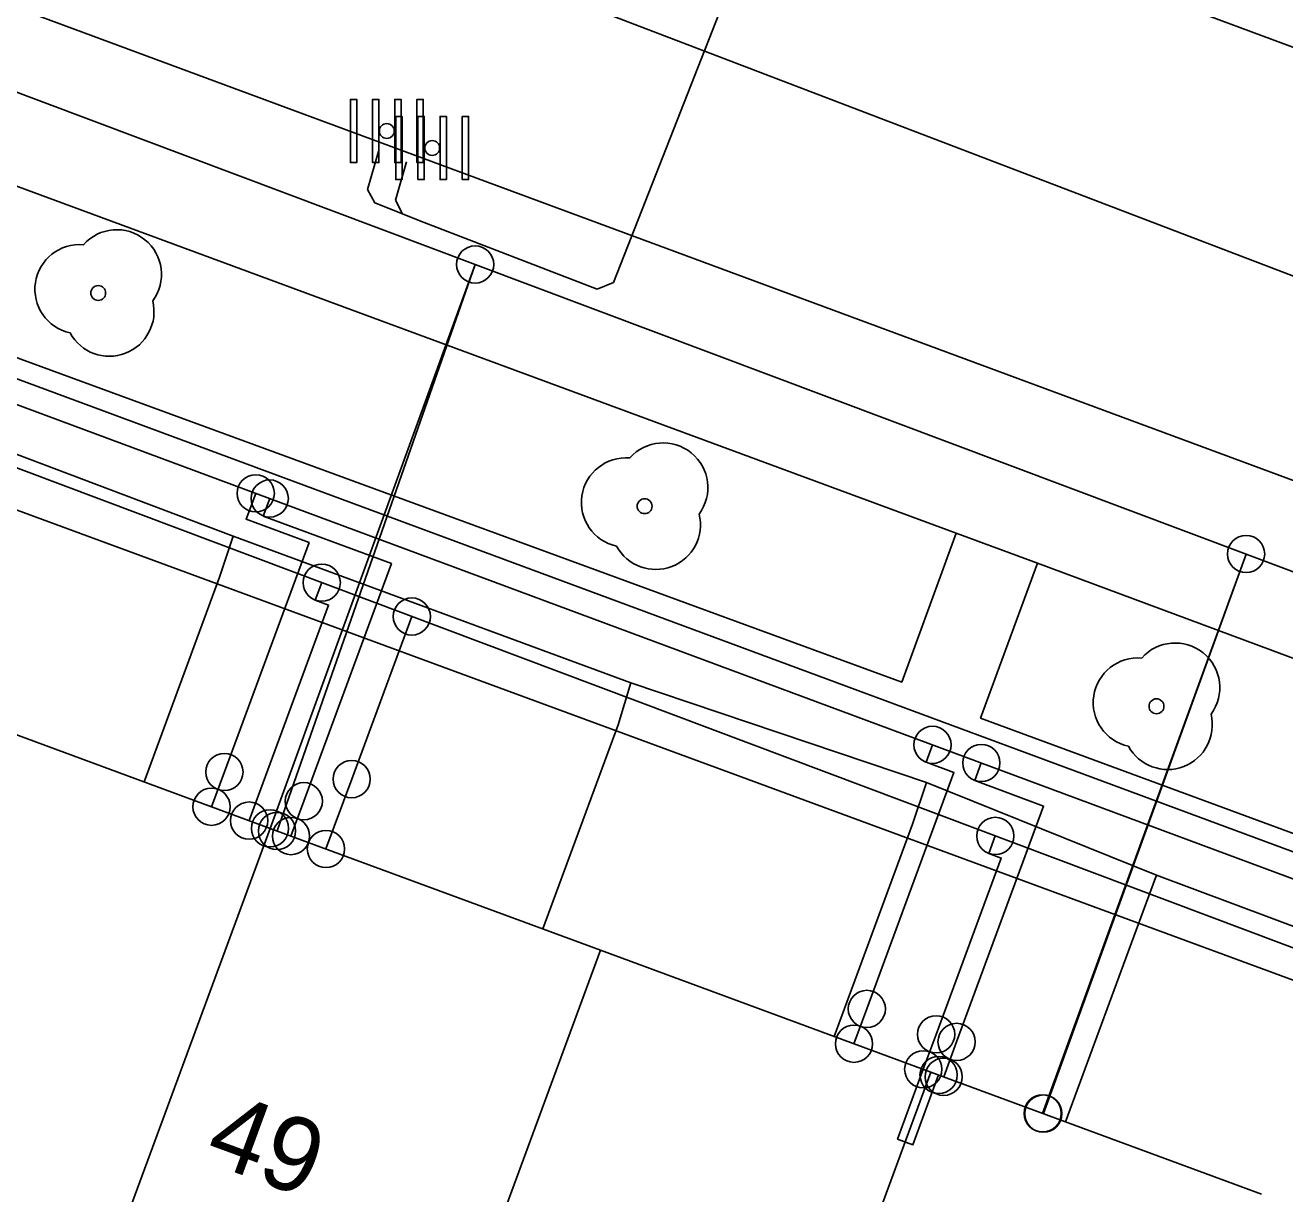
# Model space of a CAD drawing. Extents: x 192672 to 192910, y 446344 to 446512.
# Drawn here: x 192686.52 to 192703.44, y 446398.88 to 446414.58 of the extents above; entities that cross this region are included whole.
import ezdxf

# ---------------------------------------------------------------- set-up
doc = ezdxf.new("R2010")
doc.units = 0
for name, color, linetype in [('B-OI-KL-BUISLEIDING_OLIEGASCHEMICALIEN_GASLAGEDRUK-G', 7, 'Continuous'), ('B-OI-KL-DATA-G', 7, 'Continuous'), ('B-OI-KL-DATA_GTWP-S', 7, 'Continuous'), ('B-OI-KL-DATA_KABELBED-G', 7, 'Continuous'), ('B-OI-KL-DATA_MOF-S', 7, 'Continuous'), ('B-OI-KL-ET_LS-G', 7, 'Continuous'), ('B-OI-KL-ET_LS_DELIVERYPOINT-S', 7, 'Continuous'), ('B-OI-KL-ET_LS_MOF-S', 7, 'Continuous'), ('B-OI-KL-GAS_LD_AFTAKZADEL-S', 7, 'Continuous'), ('B-OI-KL-GAS_LD_DELIVERYPOINT-S', 7, 'Continuous'), ('B-OI-KL-GAS_LD_OVERGANGSSTUK-S', 7, 'Continuous'), ('B-OI-RI-RIOOLVRIJVERVAL-G', 7, 'Continuous'), ('boom', 7, 'Continuous'), ('Default', 7, 'Continuous'), ('huisnummerreeks BGT', 7, 'Continuous'), ('kant open verharding', 7, 'Continuous'), ('kant verharding', 7, 'Continuous'), ('kolk', 7, 'Continuous'), ('pand op maaiveld vlak', 7, 'Continuous'), ('verkeerseiland - berm', 7, 'Continuous')]:
    doc.layers.add(name, color=color, linetype=linetype)

# ---------------------------------------------------------------- blocks, each defined once
blk = doc.blocks.new('B-OI-KL-GAS_LD_AFTAKZADEL-S')
at = {"layer": 'Default'}
blk.add_circle((0, 0), 0.25, dxfattribs=at)
blk = doc.blocks.new('B-OI-KL-GAS_LD_DELIVERYPOINT-S')
at = {"layer": 'Default'}
blk.add_circle((0, 0), 0.25, dxfattribs=at)
blk = doc.blocks.new('B-OI-KL-GAS_LD_OVERGANGSSTUK-S')
at = {"layer": 'Default'}
blk.add_circle((0, 0), 0.25, dxfattribs=at)
blk = doc.blocks.new('B-OI-KL-ET_LS_DELIVERYPOINT-S')
at = {"layer": 'Default'}
blk.add_circle((0, 0), 0.25, dxfattribs=at)
blk = doc.blocks.new('B-OI-KL-ET_LS_MOF-S')
at = {"layer": 'Default'}
blk.add_circle((0, 0), 0.25, dxfattribs=at)
blk = doc.blocks.new('B-OI-KL-DATA_GTWP-S')
at = {"layer": 'Default'}
blk.add_circle((0, 0), 0.25, dxfattribs=at)
blk = doc.blocks.new('B-OI-KL-DATA_MOF-S')
at = {"layer": 'Default'}
blk.add_circle((0, 0), 0.25, dxfattribs=at)

msp = doc.modelspace()

# ---------------------------------------------------------------- linework, layer by layer
at = {"layer": 'B-OI-KL-BUISLEIDING_OLIEGASCHEMICALIEN_GASLAGEDRUK-G'}
msp.add_line((192675.743, 446413.446), (192709.208, 446401.012), dxfattribs=at)
for points in [[(192689.616, 446408.292), (192689.487, 446407.946), (192690.332, 446407.632), (192689.195, 446404.549)], [(192689.804, 446408.223), (192689.716, 446407.988), (192691.439, 446407.349), (192690.262, 446404.157)], [(192698.709, 446404.914), (192698.622, 446404.68), (192698.997, 446404.54), (192697.827, 446401.366)], [(192689.195, 446404.549), (192689.022, 446404.082)], [(192699.365, 446404.67), (192699.278, 446404.436), (192700.202, 446404.092), (192699.033, 446400.923)], [(192690.262, 446404.157), (192690.089, 446403.688)], [(192697.827, 446401.366), (192697.654, 446400.898)], [(192699.033, 446400.923), (192698.86, 446400.454)]]:
    msp.add_lwpolyline(points, dxfattribs=at)
at = {"layer": 'B-OI-KL-DATA-G'}
for points in [[(192685.635, 446409.106), (192689.311, 446407.716)], [(192689.311, 446407.716), (192689.13, 446407.165), (192688.116, 446404.416)], [(192689.311, 446407.716), (192694.658, 446405.746)], [(192694.658, 446405.746), (192694.485, 446405.183), (192693.474, 446402.441)], [(192694.658, 446405.746), (192698.63, 446404.409)], [(192698.63, 446404.409), (192698.441, 446403.846), (192697.389, 446400.996)], [(192698.63, 446404.409), (192701.719, 446403.161)], [(192701.719, 446403.161), (192701.541, 446402.678), (192700.498, 446399.849)], [(192701.719, 446403.161), (192707.348, 446401.058)]]:
    msp.add_lwpolyline(points, dxfattribs=at)
at = {"layer": 'B-OI-KL-DATA_KABELBED-G'}
for points in [[(192733.82, 446395.718), (192726.444, 446398.553), (192717.381, 446402.036), (192715.981, 446402.574), (192711.535, 446404.244), (192702.923, 446407.477), (192692.564, 446411.367), (192684.205, 446414.506), (192682.207, 446415.256), (192682.206, 446415.257), (192675.743, 446417.684)], [(192692.564, 446411.367), (192689.808, 446403.792)], [(192692.564, 446411.367), (192689.902, 446403.757)], [(192702.923, 446407.477), (192700.189, 446399.963)], [(192702.923, 446407.477), (192700.199, 446399.96)]]:
    msp.add_lwpolyline(points, dxfattribs=at)
at = {"layer": 'B-OI-KL-ET_LS-G'}
for points in [[(192705.001, 446404.897), (192704.48, 446404.329), (192704.196, 446403.239), (192682.97, 446411.104), (192687.329, 446422.57), (192687.898, 446423.091)], [(192675.743, 446412.643), (192733.67, 446390.862), (192732.765, 446387.575)], [(192690.503, 446407.093), (192690.415, 446406.859), (192690.595, 446406.791), (192689.527, 446403.896)], [(192691.713, 446406.638), (192690.905, 446404.453)], [(192690.905, 446404.453), (192690.559, 446403.515)], [(192699.553, 446403.69), (192699.465, 446403.456), (192699.632, 446403.393), (192698.758, 446401.024)], [(192698.758, 446401.024), (192698.585, 446400.555)], [(192698.585, 446400.555), (192698.239, 446399.617), (192698.445, 446399.541), (192698.791, 446400.479)]]:
    msp.add_lwpolyline(points, dxfattribs=at)
at = {"layer": 'B-OI-RI-RIOOLVRIJVERVAL-G'}
for points in [[(192696.836, 446417.278), (192694.422, 446411.124)], [(192692.66, 446415.38), (192716.55, 446406.25)], [(192691.878, 446411.931), (192691.218, 446412.194), (192691.119, 446412.374), (192691.266, 446412.887)], [(192691.494, 446412.233), (192691.641, 446412.746)], [(192691.59, 446412.046), (192691.494, 446412.233)], [(192694.202, 446411.036), (192691.878, 446411.931)], [(192694.202, 446411.036), (192694.422, 446411.124)]]:
    msp.add_lwpolyline(points, dxfattribs=at)
at = {"layer": 'boom'}
for centre in [(192687.499, 446410.984), (192694.841, 446408.12), (192701.719, 446405.432)]:
    msp.add_circle(centre, 0.1, dxfattribs=at)
for centre, radius, start, end in [((192687.749, 446411.234), 0.6, 323.5446, 138.4658), ((192687.249, 446411.034), 0.6, 85.137, 257.7544), ((192687.499, 446410.984), 0.1, 0, 180), ((192687.499, 446410.984), 0.1, 180, 0), ((192687.649, 446410.734), 0.6, 208.5058, 13.8356), ((192695.091, 446408.37), 0.6, 323.5446, 138.4658), ((192694.591, 446408.17), 0.6, 85.137, 257.7544), ((192694.841, 446408.12), 0.1, 0, 180), ((192694.841, 446408.12), 0.1, 180, 0), ((192694.991, 446407.87), 0.6, 208.5058, 13.8356), ((192701.969, 446405.682), 0.6, 323.5446, 138.4658), ((192701.469, 446405.482), 0.6, 85.137, 257.7544), ((192701.719, 446405.432), 0.1, 0, 180), ((192701.719, 446405.432), 0.1, 180, 0), ((192701.869, 446405.182), 0.6, 208.5058, 13.8356)]:
    msp.add_arc(centre, radius, start, end, dxfattribs=at)
at = {"layer": 'kant open verharding'}
msp.add_lwpolyline([(192675.743, 446411.995), (192713.029, 446398.263), (192714.204, 446397.83), (192714.097, 446397.514)], dxfattribs=at)
at = {"layer": 'kant verharding'}
for p, q in [((192675.743, 446424.623), (192733.082, 446403.313)), ((192675.743, 446418.762), (192731.114, 446398.266)), ((192700.122, 446407.353), (192699.029, 446407.759))]:
    msp.add_line(p, q, dxfattribs=at)
at = {"layer": 'kolk'}
for points in [[(192690.973, 446413.16), (192690.973, 446413.585), (192690.888, 446413.585), (192690.888, 446413.16), (192690.888, 446412.735), (192690.973, 446412.735)], [(192691.271, 446413.16), (192691.271, 446413.585), (192691.186, 446413.585), (192691.186, 446413.16), (192691.186, 446412.735), (192691.271, 446412.735)], [(192691.568, 446413.16), (192691.568, 446413.585), (192691.483, 446413.585), (192691.483, 446413.16), (192691.483, 446412.735), (192691.568, 446412.735)], [(192691.866, 446413.16), (192691.866, 446413.585), (192691.781, 446413.585), (192691.781, 446413.16), (192691.781, 446412.735), (192691.866, 446412.735)], [(192691.583, 446412.932), (192691.583, 446413.357), (192691.498, 446413.357), (192691.498, 446412.932), (192691.498, 446412.507), (192691.583, 446412.507)], [(192691.881, 446412.932), (192691.881, 446413.357), (192691.796, 446413.357), (192691.796, 446412.932), (192691.796, 446412.507), (192691.881, 446412.507)], [(192692.178, 446412.932), (192692.178, 446413.357), (192692.093, 446413.357), (192692.093, 446412.932), (192692.093, 446412.507), (192692.178, 446412.507)], [(192692.476, 446412.932), (192692.476, 446413.357), (192692.391, 446413.357), (192692.391, 446412.932), (192692.391, 446412.507), (192692.476, 446412.507)]]:
    msp.add_lwpolyline(points, close=True, dxfattribs=at)
for centre, start, end in [((192691.377, 446413.16), 0, 180), ((192691.377, 446413.16), 180, 0), ((192691.987, 446412.932), 0, 180), ((192691.987, 446412.932), 180, 0)]:
    msp.add_arc(centre, 0.1, start, end, dxfattribs=at)
at = {"layer": 'pand op maaiveld vlak'}
for p, q in [((192689.808, 446403.792), (192685.368, 446405.43)), ((192689.808, 446403.792), (192685.669, 446392.571)), ((192689.808, 446403.792), (192694.248, 446402.155)), ((192694.248, 446402.155), (192690.11, 446390.934)), ((192694.248, 446402.155), (192698.688, 446400.517)), ((192694.55, 446389.296), (192698.688, 446400.517)), ((192703.129, 446398.879), (192698.688, 446400.517))]:
    msp.add_line(p, q, dxfattribs=at)
at = {"layer": 'verkeerseiland - berm'}
for p, q in [((192699.029, 446407.759), (192683.929, 446413.333)), ((192714.516, 446402.006), (192700.122, 446407.353))]:
    msp.add_line(p, q, dxfattribs=at)
for points in [[(192699.029, 446407.759), (192698.296, 446405.758), (192683.182, 446411.296), (192683.929, 446413.333)], [(192714.516, 446402.006), (192713.762, 446399.96), (192699.355, 446405.274), (192700.122, 446407.353)]]:
    msp.add_lwpolyline(points, dxfattribs=at)

# ---------------------------------------------------------------- block references
at = {"layer": 'B-OI-KL-DATA_GTWP-S'}
for p in [(192692.564, 446411.367), (192692.564, 446411.367), (192702.923, 446407.477), (192702.923, 446407.477), (192689.808, 446403.792), (192689.902, 446403.757), (192700.189, 446399.963), (192700.199, 446399.96)]:
    msp.add_blockref('B-OI-KL-DATA_GTWP-S', p, dxfattribs=at)
at = {"layer": 'B-OI-KL-DATA_MOF-S'}
for p in [(192692.564, 446411.367), (192702.923, 446407.477)]:
    msp.add_blockref('B-OI-KL-DATA_MOF-S', p, dxfattribs=at)
at = {"layer": 'B-OI-KL-ET_LS_DELIVERYPOINT-S'}
for p in [(192689.527, 446403.896), (192690.559, 446403.515), (192698.585, 446400.555), (192698.791, 446400.479)]:
    msp.add_blockref('B-OI-KL-ET_LS_DELIVERYPOINT-S', p, dxfattribs=at)
at = {"layer": 'B-OI-KL-ET_LS_MOF-S'}
for p in [(192690.503, 446407.093), (192691.713, 446406.638), (192690.905, 446404.453), (192699.553, 446403.69), (192698.758, 446401.024)]:
    msp.add_blockref('B-OI-KL-ET_LS_MOF-S', p, dxfattribs=at)
at = {"layer": 'B-OI-KL-GAS_LD_AFTAKZADEL-S'}
for p in [(192689.616, 446408.292), (192689.804, 446408.223), (192698.709, 446404.914), (192699.365, 446404.67)]:
    msp.add_blockref('B-OI-KL-GAS_LD_AFTAKZADEL-S', p, dxfattribs=at)
at = {"layer": 'B-OI-KL-GAS_LD_DELIVERYPOINT-S'}
for p in [(192689.022, 446404.082), (192690.089, 446403.688), (192697.654, 446400.898), (192698.86, 446400.454)]:
    msp.add_blockref('B-OI-KL-GAS_LD_DELIVERYPOINT-S', p, dxfattribs=at)
at = {"layer": 'B-OI-KL-GAS_LD_OVERGANGSSTUK-S'}
for p in [(192689.195, 446404.549), (192690.262, 446404.157), (192697.827, 446401.366), (192699.033, 446400.923)]:
    msp.add_blockref('B-OI-KL-GAS_LD_OVERGANGSSTUK-S', p, dxfattribs=at)

# ---------------------------------------------------------------- texts
at = {"layer": 'huisnummerreeks BGT'}
msp.add_text('49', height=1, rotation=339.8, dxfattribs=at).set_placement((192688.897, 446399.331))

doc.saveas('drawing.dxf')
